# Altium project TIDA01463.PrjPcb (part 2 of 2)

## Sheet TIDA-01463_SH1.SchDoc: PoE Front End
size 431 x 279 mm; Date: Not shown in title block; ApprovedBy: Not shown in title block; CheckedBy: Not shown in title block; Author: Not shown in title block; CompanyName: Not shown in title block; Engineer: Not shown in title block; Organization: Not shown in title block; Address1: Not shown in title block; Address2: Not shown in title block; Address3: Not shown in title block; Address4: Not shown in title block; DocumentNumber: 3; Revision: Use project parameter SCH_Rev; SheetNumber: 3; SheetTotal: 6; PageSetup: Record=PageOptions¦CenterHorizontal=True¦CenterVertical=True¦PrintScale=1.00¦XCorrection=1.00¦YCorrection=1.00¦PrintKind=0¦BorderSize=5000000¦LeftOffset=0¦BottomOffset=0¦Orientation=2¦PaperLength=1000¦PaperWidth=1000¦Scale=100¦PaperSource=15¦PrintQuality=600¦MediaType=1¦DitherType=10¦PaperKind=Letter¦PrintScaleMode=1
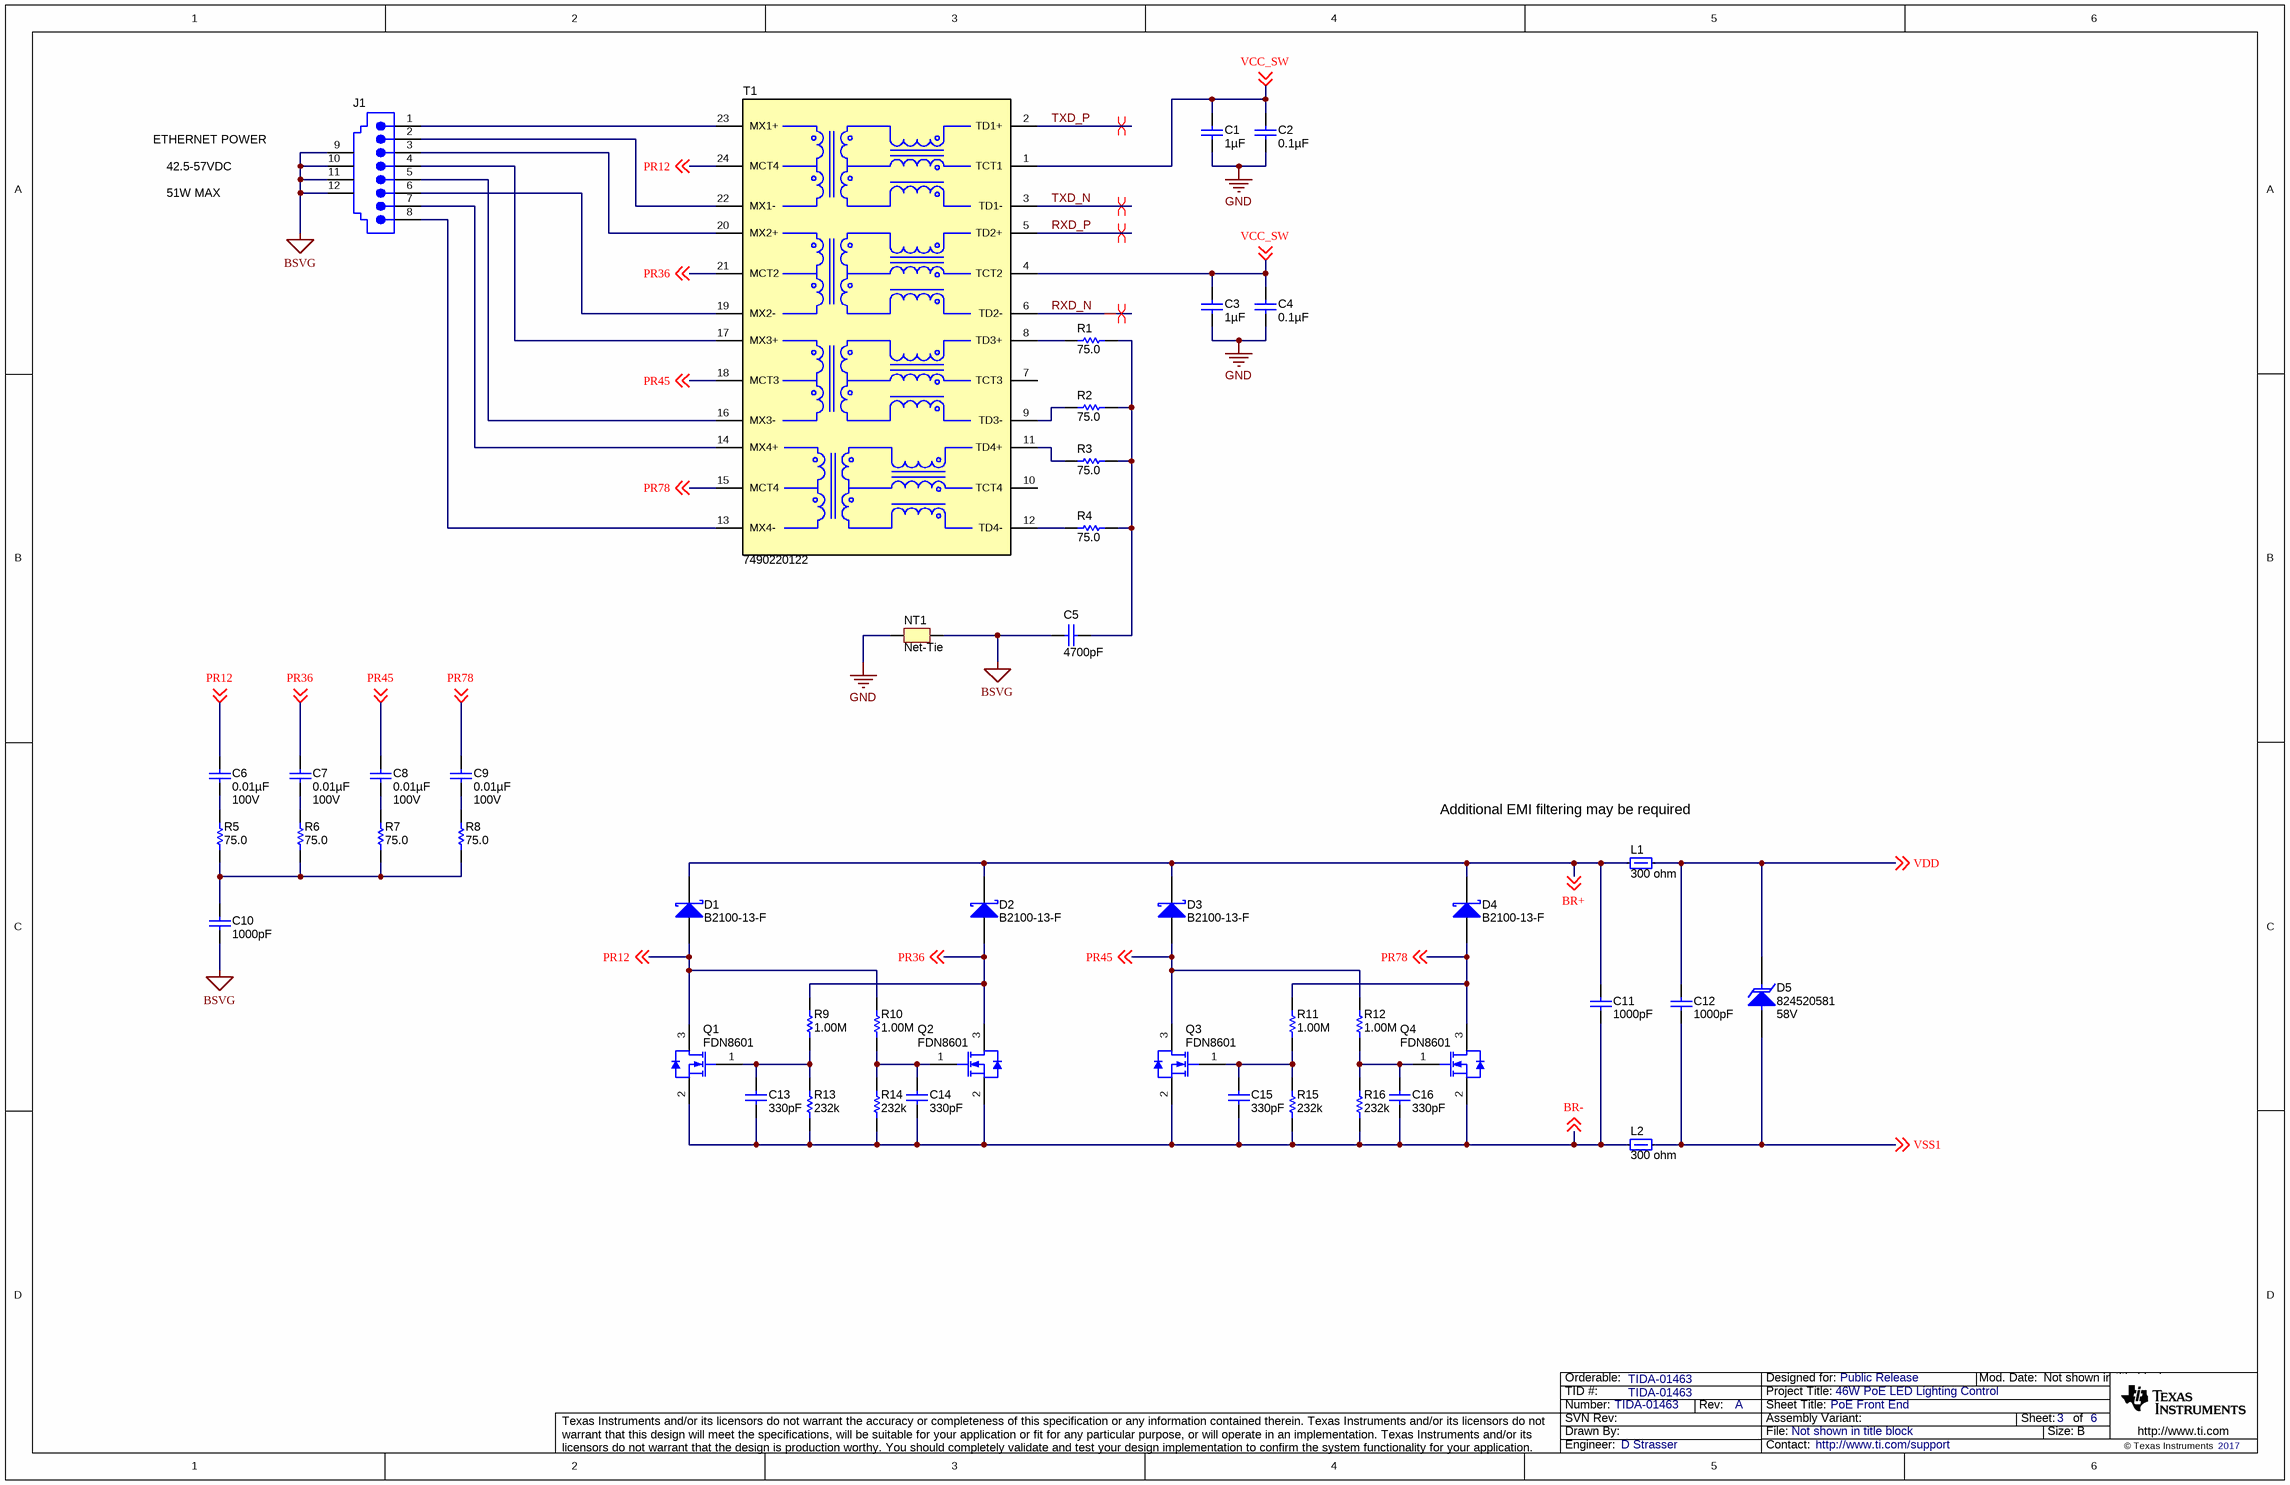
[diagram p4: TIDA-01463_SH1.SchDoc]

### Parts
C1  ValueDisplayed: 1µF  [0402]  (hidden comment: C1005X5R1A105K050BB)
C2  ValueDisplayed: 0.1µF  [0402]  (hidden comment: 885012205037)
C3  ValueDisplayed: 1µF  [0402]  (hidden comment: C1005X5R1A105K050BB)
C4  ValueDisplayed: 0.1µF  [0402]  (hidden comment: 885012205037)
C5  ValueDisplayed: 4700pF  [1812_254]  (hidden comment: 1812GC472KAT1A)
C6  ValueDisplayed: 0.01µF  Value2: 100V  [0603L]  (hidden comment: GRM188R72A103KA01D)
C7  ValueDisplayed: 0.01µF  Value2: 100V  [0603L]  (hidden comment: GRM188R72A103KA01D)
C8  ValueDisplayed: 0.01µF  Value2: 100V  [0603L]  (hidden comment: GRM188R72A103KA01D)
C9  ValueDisplayed: 0.01µF  Value2: 100V  [0603L]  (hidden comment: GRM188R72A103KA01D)
C10  ValueDisplayed: 1000pF  [1812]  (hidden comment: GR443QR73D102KW01L)
C11  ValueDisplayed: 1000pF  [0603L]  (hidden comment: C1608X7R2A102K080AA)
C12  ValueDisplayed: 1000pF  [0603L]  (hidden comment: C1608X7R2A102K080AA)
C13  ValueDisplayed: 330pF  [0603L]  (hidden comment: 885012006060)
C14  ValueDisplayed: 330pF  [0603L]  (hidden comment: 885012006060)
C15  ValueDisplayed: 330pF  [0603L]  (hidden comment: 885012006060)
C16  ValueDisplayed: 330pF  [0603L]  (hidden comment: 885012006060)
D1  B2100-13-F  [SMB]
D2  B2100-13-F  [SMB]
D3  B2100-13-F  [SMB]
D4  B2100-13-F  [SMB]
D5  824520581  value 58V  [DO214-AA-600W_UNI]
J1  1-406541-1  [TEC_1-406541-1]  (value not drawn)
L1  value 300 ohm  [WE-CBF_0603]  (hidden comment: 742792641)
L2  value 300 ohm  [WE-CBF_0603]  (hidden comment: 742792641)
NT1  Net-Tie  [Net-Tie_0805_HV_NoOverlay]  (net tie, no BOM)
Q1  FDN8601  [SSOT-3]
Q2  FDN8601  [SSOT-3]
Q3  FDN8601  [SSOT-3]
Q4  FDN8601  [SSOT-3]
R1  value 75.0  [0603L]  (hidden comment: CRCW060375R0FKEA)
R2  value 75.0  [0603L]  (hidden comment: CRCW060375R0FKEA)
R3  value 75.0  [0603L]  (hidden comment: CRCW060375R0FKEA)
R4  value 75.0  [0603L]  (hidden comment: CRCW060375R0FKEA)
R5  value 75.0  [0603L]  (hidden comment: CRCW060375R0FKEA)
R6  value 75.0  [0603L]  (hidden comment: CRCW060375R0FKEA)
R7  value 75.0  [0603L]  (hidden comment: CRCW060375R0FKEA)
R8  value 75.0  [0603L]  (hidden comment: CRCW060375R0FKEA)
R9  ValueDisplayed: 1.00M  [0603L]  (hidden comment: CRCW06031M00FKEA)
R10  ValueDisplayed: 1.00M  [0603L]  (hidden comment: CRCW06031M00FKEA)
R11  ValueDisplayed: 1.00M  [0603L]  (hidden comment: CRCW06031M00FKEA)
R12  ValueDisplayed: 1.00M  [0603L]  (hidden comment: CRCW06031M00FKEA)
R13  ValueDisplayed: 232k  [0603L]  (hidden comment: CRCW0603232KFKEA)
R14  ValueDisplayed: 232k  [0603L]  (hidden comment: CRCW0603232KFKEA)
R15  ValueDisplayed: 232k  [0603L]  (hidden comment: CRCW0603232KFKEA)
R16  ValueDisplayed: 232k  [0603L]  (hidden comment: CRCW0603232KFKEA)
T1  7490220122  [Wurth_7490220122]

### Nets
BSVG: C5.1 C10.2 J1.9 J1.10 J1.11 J1.12 NT1.1
GND: C1.2 C2.2 C3.2 C4.2 NT1.2
BR+: C11.1 D1.1(K) D2.1(K) D3.1(K) D4.1(K) L1.1 ; off-sheet BR+
BR-: C11.2 C13.2 C14.2 C15.2 C16.2 L2.1 Q1.2(S) Q2.2(S) Q3.2(S) Q4.2(S) R13.1 R14.1 R15.1 R16.1 ; off-sheet BR-
PR12: C6.1 D1.2(A) Q1.3(D) R10.2 T1.24(MCT4) ; off-sheet PR12
PR36: C7.1 D2.2(A) Q2.3(D) R9.2 T1.21(MCT2) ; off-sheet PR36
PR45: C8.1 D3.2(A) Q3.3(D) R12.2 T1.18(MCT3) ; off-sheet PR45
PR78: C9.1 D4.2(A) Q4.3(D) R11.2 T1.15(MCT4) ; off-sheet PR78
RXD_N: T1.6(TD2-)
RXD_P: T1.5(TD2+)
TXD_N: T1.3(TD1-)
TXD_P: T1.2(TD1+)
VCC_SW: C1.1 C2.1 C3.1 C4.1 T1.1(TCT1) T1.4(TCT2) ; off-sheet VCC_SW
VDD: C12.1 D5.1(K) L1.2 ; off-sheet VDD
VSS1: C12.2 D5.2(A) L2.2 ; off-sheet VSS1
NetC5_2: C5.2 R1.1 R2.1 R3.1 R4.1
NetC6_2: C6.2 R5.2
NetC7_2: C7.2 R6.2
NetC8_2: C8.2 R7.2
NetC9_2: C9.2 R8.2
NetC10_1: C10.1 R5.1 R6.1 R7.1 R8.1
NetC13_1: C13.1 Q1.1(G) R9.1 R13.2
NetC14_1: C14.1 Q2.1(G) R10.1 R14.2
NetC15_1: C15.1 Q3.1(G) R11.1 R15.2
NetC16_1: C16.1 Q4.1(G) R12.1 R16.2
NetJ1_1: J1.1 T1.23(MX1+)
NetJ1_2: J1.2 T1.22(MX1-)
NetJ1_3: J1.3 T1.20(MX2+)
NetJ1_4: J1.4 T1.17(MX3+)
NetJ1_5: J1.5 T1.16(MX3-)
NetJ1_6: J1.6 T1.19(MX2-)
NetJ1_7: J1.7 T1.14(MX4+)
NetJ1_8: J1.8 T1.13(MX4-)
NetR1_2: R1.2 T1.8(TD3+)
NetR2_2: R2.2 T1.9(TD3-)
NetR3_2: R3.2 T1.11(TD4+)
NetR4_2: R4.2 T1.12(TD4-)

Not connected (* = marked no-connect by the designer): T1 7(TCT3) 10(TCT4)

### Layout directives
differential pair: RXD_N, RXD_P, TXD_N, TXD_P

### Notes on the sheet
- ETHERNET POWER
- 42.5-57VDC
- 51W MAX
- (near L1) Additional EMI filtering may be required

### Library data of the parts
C1 C3 = C1005X5R1A105K050BB: CAP, CERM, 1 µF, 10 V, +/- 10%, X5R, 0402; Manufacturer: TDK; Polarized: N; CompType: Capacitor; Value: 1uF; U/M: EA; Cap_F: 0.000001; Tolerance_%: 10; Value1: Unknown; Value2: 10V; TaMin_C: -55; TaMax_C: 85; SizeArea_mm2: 0.5; SizeAreaWB_mm2: 3; SizeX_mm: 1; SizeZ_mm: 0.6; AEC Category: Q200
C2 C4 = 885012205037: CAP, CERM, 0.1 µF, 16 V, +/- 10%, X7R, 0402; Manufacturer: Wurth Elektronik; Polarized: N; CompType: Capacitor; Value: 0.1uF; U/M: EA; Cap_F: 0.0000001; Tolerance_%: 10; Value1: Unknown; VDC_V: 16; Value2: 16V; TaMin_C: -55; TaMax_C: 125; SizeArea_mm2: 0.5; SizeAreaWB_mm2: 3; SizeX_mm: 1; SizeZ_mm: 0.6; AEC Category: Q200
C5 = 1812GC472KAT1A: CAP, CERM, 4700 pF, 2000 V, +/- 10%, X7R, 1812; Manufacturer: AVX; Polarized: N; CompType: Capacitor; Value: 4700pF; U/M: EA; Cap_F: 0.0000000047; Tolerance_%: 10; Value1: Unknown; VDC_V: 2000; Value2: 2000V; TaMin_C: -55; TaMax_C: 125; Cap_Case: 1812; SizeArea_mm2: 14.4; SizeAreaWB_mm2: 23.1; SizeX_mm: 4.5; SizeY_mm: 3.2; SizeZ_mm: 2.54; AEC Category: Q200
C6-C9 = GRM188R72A103KA01D: CAP, CERM, 0.01 µF, 100 V, +/- 10%, X7R, 0603; Manufacturer: MuRata; Polarized: N; CompType: Capacitor; Value: 0.01uF; U/M: EA; Cap_F: 0.00000001; Tolerance_%: 10; Value1: Unknown; VDC_V: 100; TaMin_C: -55; TaMax_C: 125; Cap_Case: 0603; SizeArea_mm2: 1.28; SizeAreaWB_mm2: 4.68; SizeX_mm: 1.6; SizeY_mm: 0.8; SizeZ_mm: 1; AEC Category: Q200
C10 = GR443QR73D102KW01L: CAP, CERM, 1000 pF, 2000 V,+/- 10%, X7R, 1812; Manufacturer: MuRata; Polarized: N; CompType: Capacitor; Value: 1000pF; U/M: EA; Cap_F: 0.000000001; Tolerance_%: 10; VDC_V: 2000; Value2: 2000V; TaMin_C: -55; TaMax_C: 125; SizeArea_mm2: 14.4; SizeAreaWB_mm2: 23.1; SizeX_mm: 4.5; SizeY_mm: 3.2; SizeZ_mm: 1.35; AEC Category: Q200
C11 C12 = C1608X7R2A102K080AA: CAP, CERM, 1000 pF, 100 V, +/- 10%, X7R, 0603; Manufacturer: TDK; Polarized: N; CompType: Capacitor; Value: 1000pF; U/M: EA; Cap_F: 0.000000001; Tolerance_%: 10; Value1: Unknown; VDC_V: 100; Value2: 100V; TaMin_C: -55; TaMax_C: 125; Cap_Case: 0603; SizeArea_mm2: 1.28; SizeAreaWB_mm2: 4.68; SizeX_mm: 1.6; SizeY_mm: 0.8; SizeZ_mm: 1; AEC Category: Q200
C13-C16 = 885012006060: CAP, CERM, 330 pF, 50 V, +/- 5%, C0G/NP0, 0603; Manufacturer: Wurth Elektronik; Polarized: N; CompType: Capacitor; Value: 330pF; U/M: EA; Cap_F: 0.00000000033; Tolerance_%: 5; Value1: Unknown; VDC_V: 50; Value2: 50V; TaMin_C: -55; TaMax_C: 125; Cap_Case: 0603; AEC Category: Q200
D1-D4 = B2100-13-F: Diode, Schottky, 100 V, 2 A, SMB; Manufacturer: Diodes Inc.; Value: 100V; U/M: EA; Vf_V: 0.79; Value1: 2A; Value2: 0.79V; Io_A: 2; Vr_V: 100; TJmax_C: 150; RJC_CperW: 15; AEC Category: Q101
D5 = 824520581: Diode, TVS, Uni, 58 V, DO-214; Manufacturer: Wurth Elektronik; U/M: EA; Power_W: 5; Vr_V: 58; Value1: 5W; SizeAreaWB_mm2: 41.588; SizeArea_mm2: 19.548; SizeX_mm: 5.4; SizeY_mm: 3.62; SizeZ_mm: 2.65; AEC Category: Q101; AEC Qualified: N
J1 = 1-406541-1: RJ-45, No LED, tab up, R/A, TH; Manufacturer: TE Connectivity; SymbolCreator: x0208326; CompType: Connector; ContactFinish: Gold
L1 L2 = 742792641: Ferrite Bead, 300 ohm @ 100 MHz, 2 A, 0603; Manufacturer: Wurth Elektronik; Imax_A: 2; DCR_ohm: 0.15; Value1: 0.15 ohm; Value2: 2A; ZTyp@100MHz_Ohm: 300
NT1 = Net-Tie: Single point connection between nets.; SymbolCreator: codlsc
Q1-Q4 = FDN8601: MOSFET, N-CH, 100V, 2.7A, SSOT-3; Manufacturer: Fairchild Semiconductor; Alternate Manufacturer: None; U/M: EA; ChType: N; VdsMax_V: 100; Value1: ? ohm; Rdson45_Ohm: 0; Value2: 3 nC; QgTyp_nC: 3; Vgs_V: 20; IdsMax_A: 2.7
R1-R8 = CRCW060375R0FKEA: RES, 75.0 ohm, 1%, 0.1W, 0603; Manufacturer: Vishay-Dale; CompType: Resistor; Res_ohm: 75; Value_Code: 75R0; Tolerance_%: 1; Power_W: 0.1; TempCo: 100 ppm/C; EIA_Code: E96; U/M: EA
R9-R12 = CRCW06031M00FKEA: RES, 1.00 M, 1%, 0.1 W, 0603; Manufacturer: Vishay-Dale; CompType: Resistor; Value: 1.00Meg; Res_ohm: 1000000; Value_Code: 1M00; Tolerance_%: 1; Power_W: 0.1; Value2: 0.1W; VDC_V: 75; TempCo: 100 ppm/C; EIA_Code: E96; U/M: EA; AEC Category: Q200
R13-R16 = CRCW0603232KFKEA: RES, 232 k, 1%, 0.1 W, 0603; Manufacturer: Vishay-Dale; CompType: Resistor; Value: 232k; Res_ohm: 232000; Tolerance_%: 1; Power_W: 0.1; Value2: 0.1W; VDC_V: 75; TempCo: 100 ppm/C; EIA_Code: E96; U/M: EA; AEC Category: Q200
T1 = 7490220122: Transformer, 350 uH, SMT; Manufacturer: Wurth Elektronik; SymbolCreator: Altium; Value: 350 uH; U/M: EA

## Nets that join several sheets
GND: TIDA-01463_SH2 (38 pins), TIDA-01463_SH3 (37 pins), TIDA-01463_SH4 (20 pins), TIDA-01463_SH1 (5 pins)
ANA_DIM: TIDA-01463_SH2 (R28.1), TIDA-01463_SH3 (C50.1 R45.2 TP4.1)
BT: TIDA-01463_SH2 (U1.19), TIDA-01463_SH3 (U5.105)
BT_LED: TIDA-01463_SH2 (D8.2), TIDA-01463_SH3 (U5.119)
EPHY_CLKOUT: TIDA-01463_SH3 (R50.1), TIDA-01463_SH4 (U6.24)
EPHY_COL: TIDA-01463_SH3 (U5.71), TIDA-01463_SH4 (U6.29)
EPHY_CRS: TIDA-01463_SH3 (U5.72), TIDA-01463_SH4 (U6.27)
EPHY_INTRN: TIDA-01463_SH3 (U5.118), TIDA-01463_SH4 (U6.8)
EPHY_MDC: TIDA-01463_SH3 (U5.44), TIDA-01463_SH4 (U6.20)
EPHY_MDIO: TIDA-01463_SH3 (U5.45), TIDA-01463_SH4 (R57.2 U6.19)
EPHY_RXCK: TIDA-01463_SH3 (U5.40), TIDA-01463_SH4 (U6.25)
EPHY_RXD0: TIDA-01463_SH3 (U5.57), TIDA-01463_SH4 (R65.1 R67.2 U6.30)
EPHY_RXD1: TIDA-01463_SH3 (U5.58), TIDA-01463_SH4 (R60.1 R62.2 U6.31)
EPHY_RXD2: TIDA-01463_SH3 (U5.61), TIDA-01463_SH4 (U6.32)
EPHY_RXD3: TIDA-01463_SH3 (U5.62), TIDA-01463_SH4 (R61.1 R63.2 U6.1)
EPHY_RXDV: TIDA-01463_SH3 (U5.56), TIDA-01463_SH4 (U6.26)
EPHY_RXER: TIDA-01463_SH3 (U5.55), TIDA-01463_SH4 (U6.28)
EPHY_TXCK: TIDA-01463_SH3 (U5.51), TIDA-01463_SH4 (U6.2)
EPHY_TXD0: TIDA-01463_SH3 (U5.53), TIDA-01463_SH4 (U6.4)
EPHY_TXD1: TIDA-01463_SH3 (U5.54), TIDA-01463_SH4 (U6.5)
EPHY_TXD2: TIDA-01463_SH3 (U5.60), TIDA-01463_SH4 (U6.6)
EPHY_TXD3: TIDA-01463_SH3 (U5.59), TIDA-01463_SH4 (U6.7)
EPHY_TXEN: TIDA-01463_SH3 (U5.52), TIDA-01463_SH4 (U6.3)
PWM_DIM: TIDA-01463_SH2 (R69.1), TIDA-01463_SH3 (TP5.1 U5.43)
RXD_N: TIDA-01463_SH4 (R55.1 U6.9 U7.1 U7.10), TIDA-01463_SH1 (T1.6)
RXD_P: TIDA-01463_SH4 (R54.1 U6.10 U7.2 U7.9), TIDA-01463_SH1 (T1.5)
TPH: TIDA-01463_SH2 (U1.18), TIDA-01463_SH3 (U5.106)
TPH_LED: TIDA-01463_SH2 (D6.2), TIDA-01463_SH3 (U5.116)
TPL: TIDA-01463_SH2 (U1.17), TIDA-01463_SH3 (U5.107)
TPL_LED: TIDA-01463_SH2 (D7.2), TIDA-01463_SH3 (U5.117)
TXD_N: TIDA-01463_SH4 (R53.1 U6.11 U7.4 U7.7), TIDA-01463_SH1 (T1.3)
TXD_P: TIDA-01463_SH4 (R52.1 U6.12 U7.5 U7.6), TIDA-01463_SH1 (T1.2)
VCC_1P8: TIDA-01463_SH2 (C29.1 L5.2 U3.5), TIDA-01463_SH4 (J11.3)
VCC_3P3_EXT: TIDA-01463_SH2 (7 pins), TIDA-01463_SH3 (J8.2 J10.1), TIDA-01463_SH4 (J11.1 J12.1)
VCC_SW: TIDA-01463_SH4 (10 pins), TIDA-01463_SH1 (6 pins)
VDD: TIDA-01463_SH2 (9 pins), TIDA-01463_SH1 (C12.1 D5.1 L1.2)
VSS1: TIDA-01463_SH2 (J5.2 TP2.1), TIDA-01463_SH1 (C12.2 D5.2 L2.2)

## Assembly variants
001: not fitted D9 D11 R25 R50 R58 R61 R63 R64 R65 R66 R67 R68 SH-J2 SH-J3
